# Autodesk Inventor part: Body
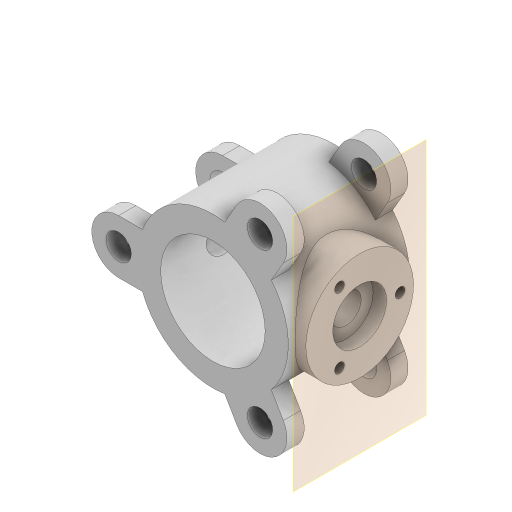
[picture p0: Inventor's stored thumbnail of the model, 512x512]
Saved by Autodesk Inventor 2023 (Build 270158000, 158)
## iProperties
Created: 2019-03
Part Number: Body
Material: Generic
Document SubType Name: Modeling
Designer: LENOVO-CADCIM
Density: 1 g/cm^3
Appearance: Default
Author: LENOVO-CADCIM
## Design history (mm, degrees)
sketch "Sketch1"
  geometry: C1 r 140 at (0, 0); C2 r 97 at (0, 0); 1 further point
  constraints: 2 centre point, 2 coincident
  dimensions: "d0" = 194 diameter of C2; "d1" = 280 diameter of C1
extrude "Extrusion1" new body sketch "Sketch1" stored distance "d2" = 225; taper "d3" = 0 deg
sketch "Sketch2"
  geometry: L1 (0, 0)-(-428, 0); L2 (-130.767, 50)-(-175, 50); L3 (-130.767, -50)-(-175, -50); C1 r 23.5 at (-175, 0); A1 r 175 centre (0, 0) between (-175, 0) and (-175, 0); A2 r 140 centre (0, 0) between (-130.767, 50) and (-130.767, -50) reference; A3 r 50 centre (-175, 0) between (-175, 50) and (-175, -50); 1 further point
  constraints: 6 end point, 6 point on circle, 3 centre point, 3 horizontal, 2 tangent, 1 coincident, 1 point on line, 1 other
  dimensions: "d4" = 350 diameter of A1; "d5" = 50 radius of A3; "d6" = 47 diameter of C1
extrude "Extrusion2" join sketch "Sketch2" distance "d7" = 32; taper "d8" = 0 deg
pattern_circular "Circular Pattern1" dims angle "d10" = 360 deg
mirror "Mirror1"
workplane "Work Plane1"
sketch "Sketch3"
  geometry: C1 r 100 at (0, 0); 1 further point
  constraints: 1 centre point, 1 coincident
  dimensions: "d13" = 200 diameter of C1
extrude "Extrusion3" join sketch "Sketch3" stored distance "d14" = 32; taper "d15" = 0 deg
sketch "Sketch4" dims "d16" = 150
  geometry: L1 (0, 0)-(102, 0); 2 further points
  constraints: 2 end point, 1 coincident, 1 horizontal, 1 horizontal alignment, 1 point on line, 2 other
hole "Hole1" sketch "Sketch4" at (75, 0) diameter "d17" = 18.376; stored, may be unused: countersink angle "d21" = 90 deg, drill point angle "d23" = 118 deg; dims "d18" = 40, "d19" = 4, "d20" = 2, "d22" = 47.3
pattern_circular "Circular Pattern2" dims angle "d25" = 360 deg
sketch "Sketch5"
  geometry: C1 r 100 at (0, 0) reference; 2 further points
  constraints: 1 coincident
hole "Hole2" sketch "Sketch5" at (0, 0) diameter "d27" = 56; stored, may be unused: countersink angle "d31" = 90 deg, drill point angle "d33" = 118 deg; dims "d28" = 6, "d29" = 100, "d30" = 25, "d32" = 310
body "Solid1"
